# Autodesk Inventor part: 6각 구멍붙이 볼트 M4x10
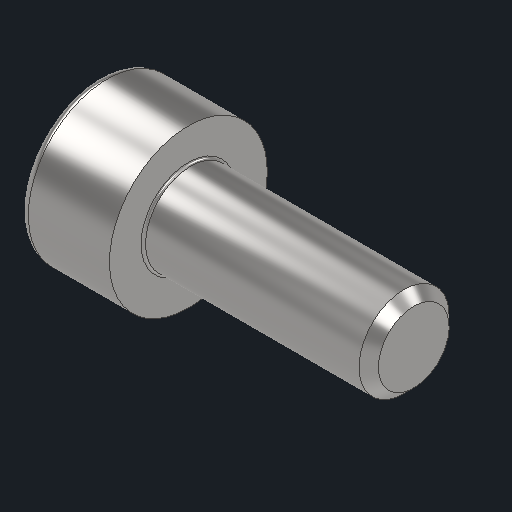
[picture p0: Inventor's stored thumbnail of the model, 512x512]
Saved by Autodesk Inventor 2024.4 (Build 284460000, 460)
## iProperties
Created: 2026-03
Part Number: 6각 구멍붙이 볼트 M4x10
Material: 강철, 연강
Description: 6각머리 태핑 나사
Document SubType Name: Modeling
Designer: user
Density: 7.85 g/cm^3
Appearance: 기본값
Author: jhkim
Sending System: Autodesk Inventor 2026
Preprocessor: ST-DEVELOPER v20.1
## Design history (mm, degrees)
feature "Solid1"
node "솔리드1"
